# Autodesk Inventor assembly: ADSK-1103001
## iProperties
Shininess: 50.0
Length Units: 11272
Angle Units: 11279
Time Units: 11290
Mass Units: 11286
Length Display Precision: 4
Angle Display Precision: 2
Compacted: True
Created: 2000-09
Part Number: ADSK-1103001
Document SubType Name: Assembly
Mass: 15.0871 g
Surface Area: 83.7511 cm^2
Volume: 5.8351 cm^3
Density: 2.58558 g/cm^3
Designer: Autodesk, Inc.
Density: 0.0
Volumn: 0.0
Area: 0.0
PropertySet Name: Model Information
Control State: 0
Master: False
Checked Out: False
Title: Carburetor
Author: Autodesk, Inc.
